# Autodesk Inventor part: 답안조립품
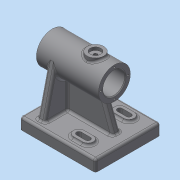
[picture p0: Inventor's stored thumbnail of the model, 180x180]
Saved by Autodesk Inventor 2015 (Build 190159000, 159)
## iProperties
Created: 2026-09
Part Number: 답안조립품
Material: 일반
Document SubType Name: Modeling
Designer: SCD-A06
Density: 1 g/cm^3
Appearance: 기본값
Author: SCD-A06
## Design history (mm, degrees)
sketch "스케치1"
  geometry: L1 (-50, -43)-(50, -43); L2 (50, -43)-(50, 43); L3 (50, 43)-(-50, 43); L4 (-50, 43)-(-50, -43); L5 (-50, -43)-(50, 43); L6 (50, -43)-(-50, 43); 1 further point
  constraints: 12 end point, 2 midpoint, 2 parallel, 1 horizontal, 1 perpendicular
  dimensions: "d0" = 100 distance of L2.end L3.end; "d1" = 86 distance of L1.end L2.end
extrude "돌출1" new body sketch "스케치1" distance "d2" = 15; taper "d3" = 0 deg
node "작업 평면1"
sketch "스케치2"
  geometry: L1 (50, 21)-(-32, 21); L2 (-32, 21)-(-32, 0); L3 (-32, 0)-(50, 0); L4 (50, 0)-(50, 21); L5 (50, 43)-(50, -43) reference; L6 (-50, -43)-(-50, 43) reference; 3 further points
  constraints: 8 end point, 2 midpoint, 2 parallel, 1 coincident, 1 collinear, 1 horizontal, 1 perpendicular, 1 point on line
  dimensions: "d5" = 82 distance of L1.start L1.end; "d7" = 42 diameter of L1 L3
revolve "회전1" sketch "스케치2" stored, may be unused: angle "d8" = 90 deg
sketch "스케치4"
  geometry: L1 (-50, -43)-(50, -43) reference; L2 (-50, 43)-(-50, -43) reference; L3 (-35, -35)-(-25, -35); L4 (-25, -35)-(-25, 35); L5 (-25, 35)-(-35, 35); L6 (-35, 35)-(-35, -35); 3 further points
  constraints: 8 end point, 2 midpoint, 2 parallel, 1 horizontal, 1 horizontal alignment, 1 perpendicular
  dimensions: "d9" = 10 distance of L3.start L3.end; "d10" = 15 distance between parallel lines of L6 L2; "d11" = 8 distance between parallel lines of L3 L1
extrude "돌출2" join sketch "스케치4" distance "d14" = 50; taper "d15" = 0 deg
sketch "스케치6"
  geometry: L1 (50, 70)-(50, 54.799) reference; L2 (0, 70)-(50, 70) reference; L3 (50, 15.201)-(50, 0) reference; L4 (0, 70)-(61.814, 55.441); L5 (0, 70)-(61.814, 70); L6 (61.814, 70)-(61.814, 55.441); L7 (50, 58.223)-(50, 54.799); A1 r 21 centre (57, 35) between (50, 15.201) and (50, 54.799) reference; A2 r 21 centre (57, 35) between (61.814, 55.441) and (50, 54.799); 1 further point
  constraints: 9 end point, 4 point on line, 3 point on circle, 1 centre point, 1 coincident, 1 collinear, 1 concentric, 1 perpendicular, 1 tangent
extrude "돌출3" cut sketch "스케치6" distance "d16" = 50; taper "d17" = 0 deg
extrude "돌출4" join sketch "스케치6" distance "d18" = 10; taper "d19" = 0 deg
sketch "스케치9"
  geometry: L1 (50, 15)-(-50, 15) reference; L2 (-35, 15)-(-28.472, 32.936); L3 (-50, 0)-(-50, 15) reference; 1 further point
  constraints: 2 end point, 1 point on line
  dimensions: "d29" = 15 distance from line of L2.start L3; "d30" = 70 deg angle of L1 L2
feature "리브1" sketch "스케치9" dims "d31" = 1, "d32" = 10, "d33" = 0, "d34" = 0, "d35" = 1, "d36" = 1
sketch "스케치11"
  geometry: 1 further point
sketch "스케치12"
  geometry: L1 (-32, 51)-(-32, 93) reference; L2 (30, 72)-(30, 86.5); L3 (30, 86.5)-(-32, 86.5); L4 (-32, 86.5)-(-32, 72); L5 (50, 72)-(50, 84.5); L6 (50, 84.5)-(30, 84.5); L7 (30, 84.5)-(30, 72); L8 (50, 51)-(50, 93) reference; L9 (-32, 72)-(30, 72); L10 (30, 72)-(50, 72); 1 further point
  constraints: 16 end point, 2 collinear, 2 parallel, 1 horizontal, 1 midpoint
  dimensions: "d41" = 62 distance between parallel lines of L2 L1; "d42" = 29 diameter of L3 L9; "d43" = 25 diameter of L6 L10
revolve "회전2" sketch "스케치12" stored, may be unused: angle "d44" = 90 deg
chamfer "모따기1" distance "d45" = 1; stored, may be unused: second distance "d46" = 2, angle "d47" = 45 deg
node "작업 평면2"
sketch "스케치13"
  geometry: L1 (-32, -21)-(-32, 21) reference; C1 r 11 at (-7, 0); 1 further point
  constraints: 1 centre point, 1 horizontal alignment
  dimensions: "d49" = 22 diameter of C1; "d50" = 25 distance from line of L1 C1.centre
extrude "돌출7" join sketch "스케치13" stored distance "d51" = 10; taper "d52" = 0 deg
hole "구멍1" diameter "d55" = 4.917; stored, may be unused: countersink angle "d59" = 90 deg, drill point angle "d61" = 118 deg; dims "d56" = 12, "d57" = 14, "d58" = 4, "d60" = 17.1, "d70" = 10, "d71" = 10
sketch "스케치14"
  geometry: C1 r 15.5 at (0, 0) reference; A1 r 18 centre (0, 0) between (-18, 0) and (0, 18); 3 further points
  constraints: 4 point on circle, 1 centre point, 1 coincident
  dimensions: "d62" = 36 diameter of A1
hole "구멍2" sketch "스케치14" at (-18, 0), (0, 18), (18, 0), (0, -18) diameter "d63" = 2.459; stored, may be unused: countersink angle "d67" = 82 deg, drill point angle "d69" = 118 deg; dims "d64" = 8, "d65" = 3.023, "d66" = 4, "d68" = 10
sketch "스케치15"
  geometry: C1 r 13.5 at (0, 0) reference; A1 r 18 centre (0, 0) between (18, 0) and (0, 18); 3 further points
  constraints: 4 point on circle, 1 centre point, 1 coincident
  dimensions: "d72" = 36 diameter of A1
hole "구멍3" sketch "스케치15" at (0, -18), (18, 0), (0, 18), (-18, 0) diameter "d73" = 2.459; stored, may be unused: countersink angle "d77" = 82 deg, drill point angle "d79" = 118 deg; dims "d74" = 8, "d75" = 3.023, "d76" = 4, "d78" = 10
sketch "스케치16"
  geometry: L1 (50, -43)-(50, 43) reference; L2 (12, 27)-(24, 27); L3 (12, 20)-(24, 20); L4 (24, 34)-(12, 34); L5 (24, -27)-(12, -27); L6 (24, -34)-(12, -34); L7 (12, -20)-(24, -20); L8 (24, 30.3)-(12, 30.3); L9 (12, 23.7)-(24, 23.7); L10 (24, -23.7)-(12, -23.7); L11 (12, -30.3)-(24, -30.3); A1 r 7 centre (12, 27) between (12, 34) and (12, 20); A2 r 7 centre (24, 27) between (24, 20) and (24, 34); A3 r 7 centre (24, -27) between (24, -34) and (24, -20); A4 r 7 centre (12, -27) between (12, -20) and (12, -34); A5 r 3.3 centre (12, 27) between (12, 30.3) and (12, 23.7); A6 r 3.3 centre (24, 27) between (24, 23.7) and (24, 30.3); A7 r 3.3 centre (12, -27) between (12, -23.7) and (12, -30.3); A8 r 3.3 centre (24, -27) between (24, -30.3) and (24, -23.7); 3 further points
  constraints: 24 end point, 16 point on circle, 8 centre point, 8 tangent, 5 parallel, 2 horizontal, 2 midpoint, 1 vertical alignment, 6 other
  dimensions: "d80" = 12 distance of L4.start L4.end; "d81" = 26 distance from line of L4.start L1; "d82" = 54 distance of L5.start L2.end; "d83" = 27 vertical distance of point (0, 0) point (18, 27) (= 0.5 x d82); "d84" = 7 radius of A2; "d85" = 7 radius of A3; "d86" = 3.7 radial gap between concentric circles of A2 A6; "d87" = 3.7 radial gap between concentric circles of A3 A8
extrude "돌출8" join sketch "스케치16" distance "d88" = 3; taper "d89" = 0 deg
extrude "돌출9" cut sketch "스케치16" stored distance "d90" = 3; taper "d91" = 0 deg
fillet "모깎기1" dims "d92" = 3
fillet "모깎기2" dims "d93" = 3
fillet "모깎기3" dims "d94" = 3
fillet "모깎기4" dims "d95" = 3
fillet "모깎기5" dims "d96" = 3
sketch "스케치17"
  geometry: L1 (0, 80)-(0, 0) reference; 3 further points
  constraints: 1 horizontal alignment, 1 midpoint, 1 other
  dimensions: "d97" = 6 distance of point (6, 40) point (0, 40)
feature "엠보싱1" sketch "스케치17" dims "d0" = 100, "d1" = 86, "d98" = 0.5, "d99" = 0
node "솔리드1"
mirror "대칭1"
other parameters: "d4" = -72, "d48" = -96
